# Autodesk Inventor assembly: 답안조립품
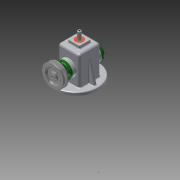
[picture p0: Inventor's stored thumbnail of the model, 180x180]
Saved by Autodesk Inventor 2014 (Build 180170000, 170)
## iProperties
Created: 2017-07
Part Number: 답안조립품
Document SubType Name: Assembly
Designer: user
Author: user
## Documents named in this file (16)
- C:\Users\user\Desktop\470708V1013\답안조립품.iam
- C:\Users\user\Desktop\470708V1013\V벨트풀리.ipt
- C:\Users\user\Desktop\470708V1013\고정핀 1.2 x  8.ipt
- C:\Users\user\Desktop\470708V1013\뒤커버.ipt
- C:\Users\user\Desktop\470708V1013\링크.ipt
- C:\Users\user\Desktop\470708V1013\멈춤나사 M3x8.ipt
- C:\Users\user\Desktop\470708V1013\베어링 12 x 32 x 10.ipt
- C:\Users\user\Desktop\470708V1013\본체.ipt
- C:\Users\user\Desktop\470708V1013\볼트 M4 x 12.ipt
- C:\Users\user\Desktop\470708V1013\부시.ipt
- C:\Users\user\Desktop\470708V1013\슬라이드.ipt
- C:\Users\user\Desktop\470708V1013\앞커버.ipt
- C:\Users\user\Desktop\470708V1013\오일실 12 25 7.ipt
- C:\Users\user\Desktop\470708V1013\키 4 x 4 x 10.ipt
- C:\Users\user\Desktop\470708V1013\편심축.ipt
- C:\Users\user\Desktop\470708V1013\핀 5 x 18.ipt
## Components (3 placed, 3 different names)
1. V벨트풀리:2
2. 고정핀 1.2 x  8:2
3. 핀 5 x 18:2
